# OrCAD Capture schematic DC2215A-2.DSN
size Custom; title: 40V, 2A SYNCHRONOUS STEP-DOWN REGULATOR WITH LOSSLESS POWER PATH; rev: 2; note: DEMO CIRCUIT 2215A
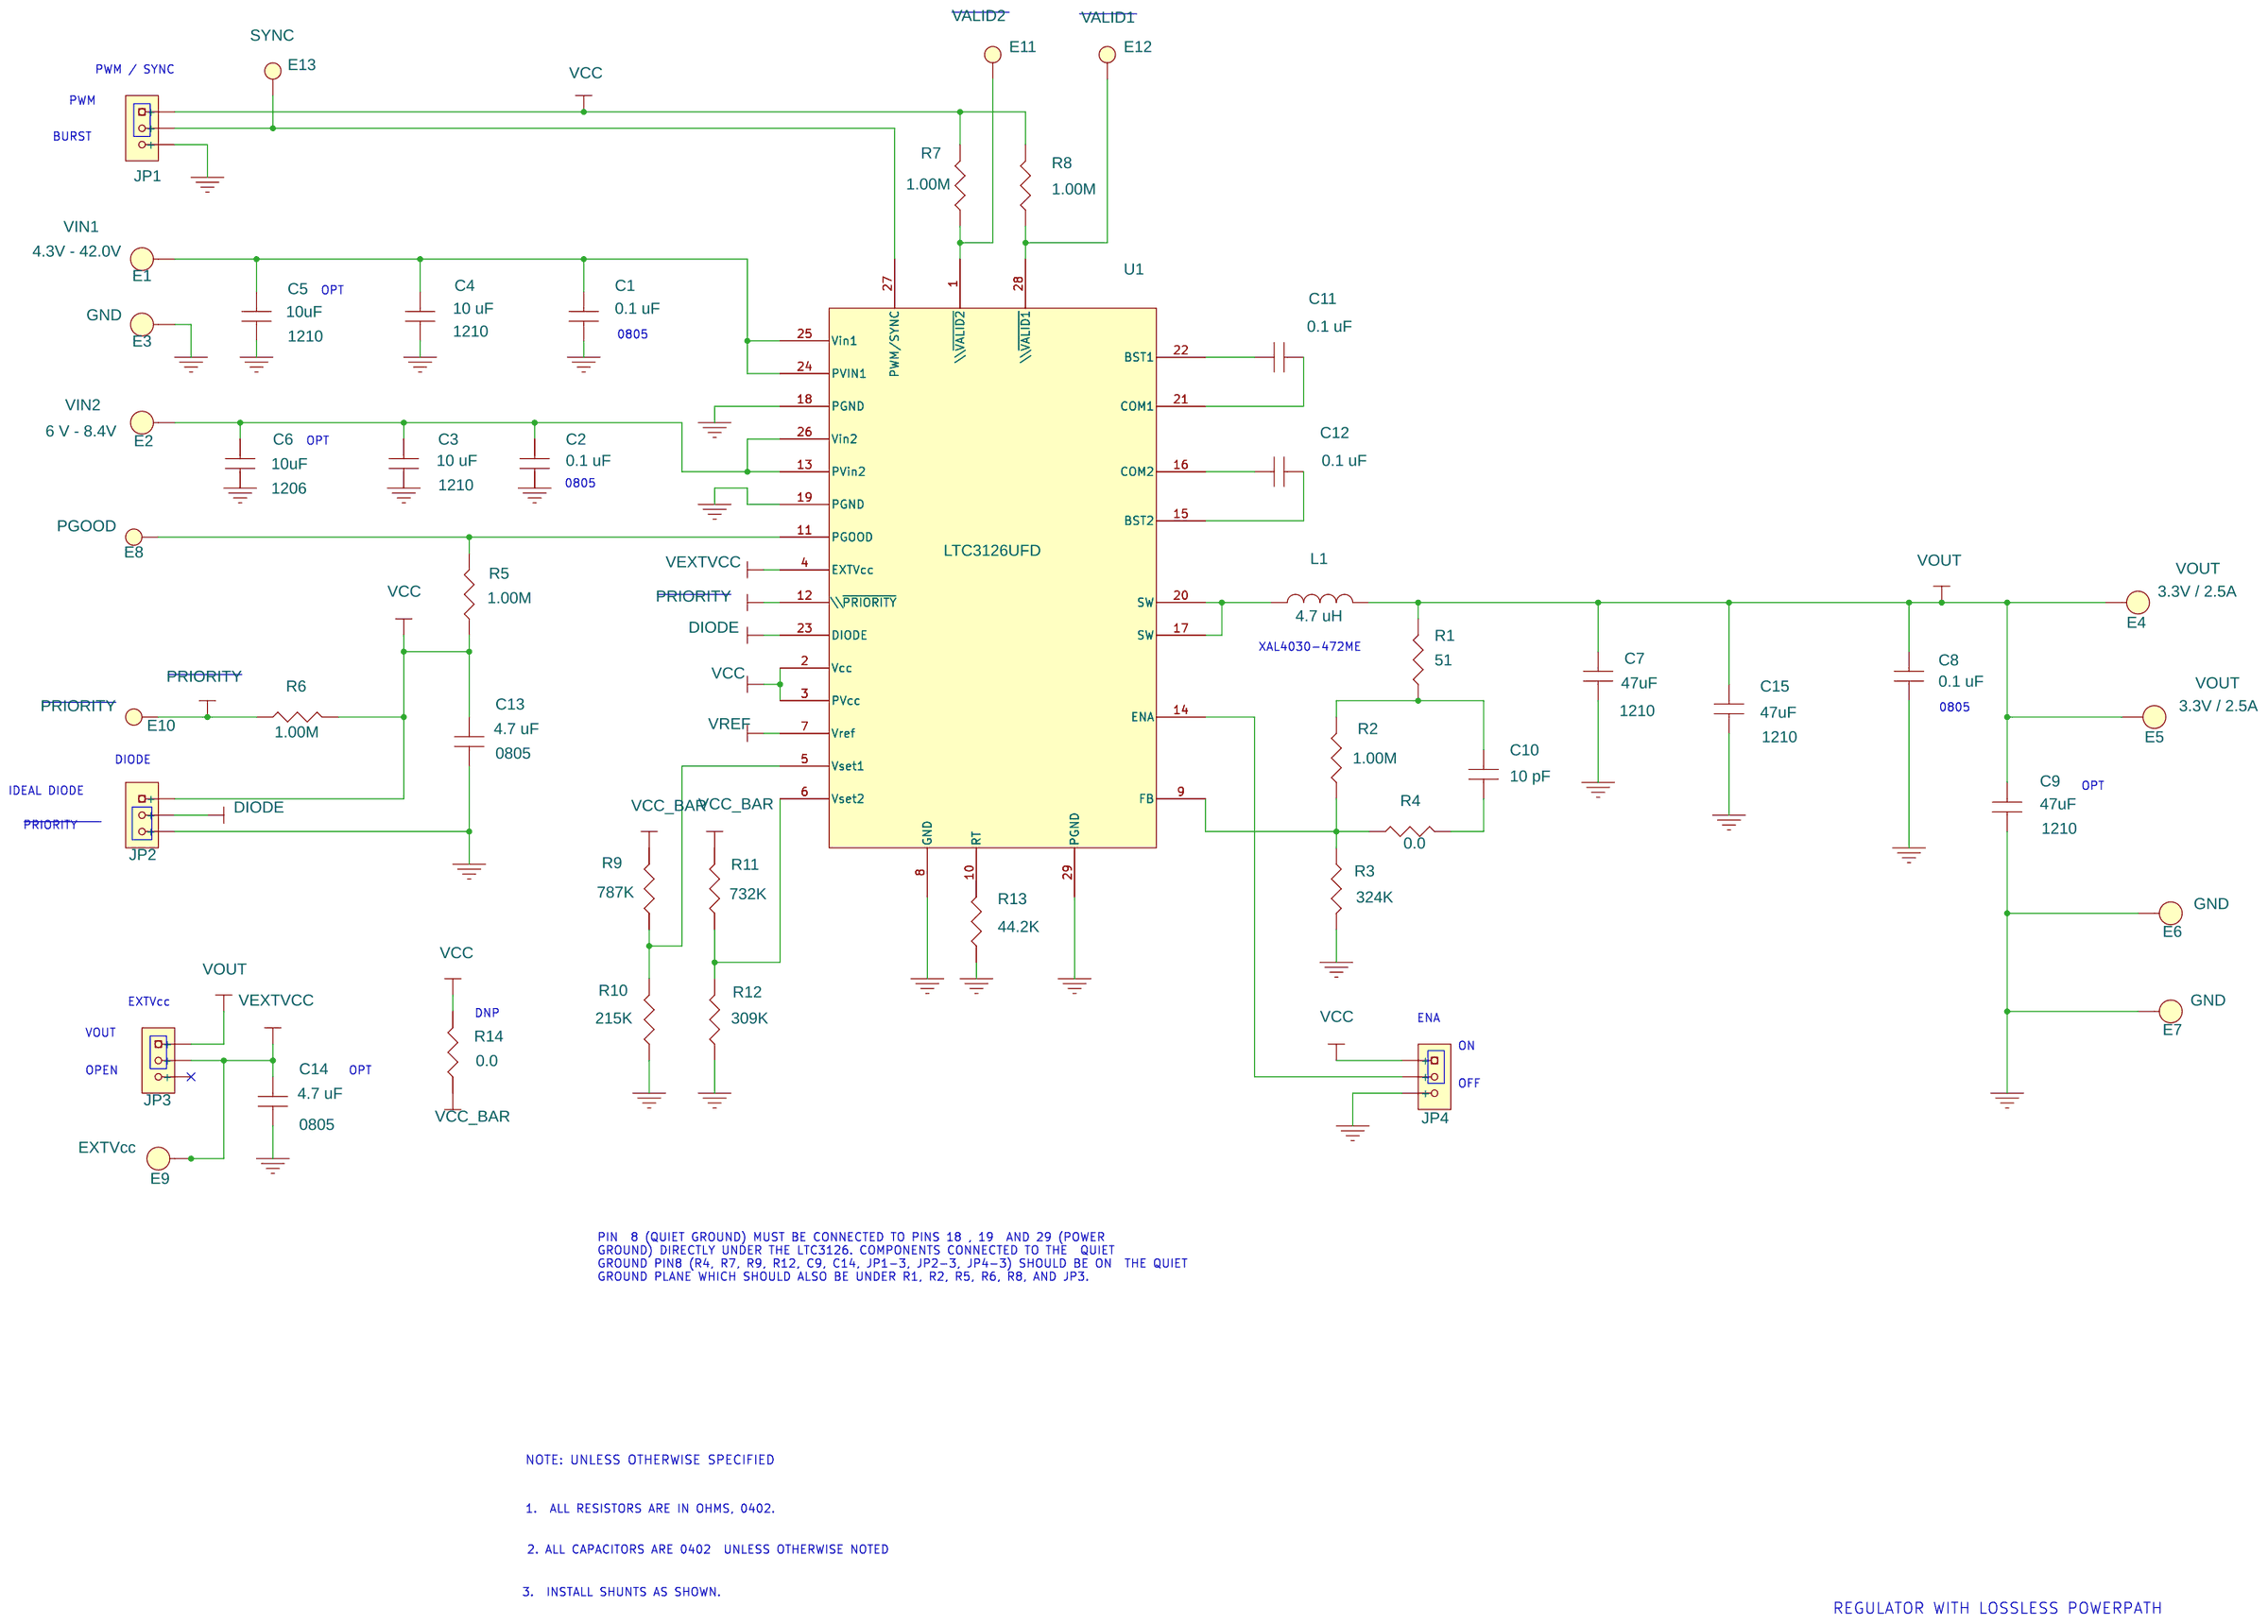
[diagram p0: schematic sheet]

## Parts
C1  0.1 uF  [0805]
C2  0.1 uF  [0805]
C3  10 uF  [1210]
C4  10 uF  [1210]
C5  10uF  [1210]
C6  10uF  [1206]
C7  47uF  [1210]
C8  0.1 uF  [0805]
C9  47uF  [1210]
C10  10 pF  [0402-SMALL]
C11  0.1 uF  [0402-SMALL]
C12  0.1 uF  [0402-SMALL]
C13  4.7 uF  [0805]
C14  4.7 uF  [0805]
C15  47uF  [1210]
E1  0.09"  [MILL-MAX-2501-2]
E2  0.09"  [MILL-MAX-2501-2]
E3  0.09"  [MILL-MAX-2501-2]
E4  0.09"  [MILL-MAX-2501-2]
E5  0.09"  [MILL-MAX-2501-2]
E6  0.09"  [MILL-MAX-2501-2]
E7  0.09"  [MILL-MAX-2501-2]
E8  PGOOD  [MILL-MAX-2308]
E9  0.09"  [MILL-MAX-2501-2]
E10  PRIORITY  [MILL-MAX-2308]
E11  VALID2  [MILL-MAX-2308]
E12  VALID1  [MILL-MAX-2308]
E13  SYNC  [MILL-MAX-2308]
JP1  ADR0  [HD1X3-079]
JP2  ADR0  [HD1X3-079]
JP3  ADR0  [HD1X3-079]
JP4  ADR0  [HD1X3-079]
L1  4.7 uH  [IND-XAL40XX]
R1  51  [0402-SMALL]
R2  1.00M  [0402-SMALL]
R3  324K  [0402-SMALL]
R4  0.0  [0402-SMALL]
R5  1.00M  [0402-SMALL]
R6  1.00M  [0402-SMALL]
R7  1.00M  [0402-SMALL]
R8  1.00M  [0402-SMALL]
R9  787K  [0402-SMALL]
R10  215K  [0402-SMALL]
R11  732K  [0402-SMALL]
R12  309K  [0402-SMALL]
R13  44.2K  [0402-SMALL]
R14  0.0  [0402-SMALL]
U1  LTC3126UFD  [LTC-UFD-28-1712]

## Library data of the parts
C1 = Capacitor_0805_2
C2 = Capacitor_0805
C3 = Capacitor_1210
C4 = Capacitor_1210_3
C5 C6 = Capacitor_1206
C7 = Capacitor_1210_1
C8 = Capacitor_0805_4
C9 = Capacitor_1210_2
C10 = CAP_0402_1
C11 = CAP_0402_2
C12 = CAP_0402
C13 = Capacitor_0805_3
C14 = Capacitor_0805_1
C15 = Capacitor_1210_4
E1 = E_2: COMPFIXED: VIN1; COMPGROUP: 4.3V - 42.0V
E2 = E_2: COMPFIXED: VIN2; COMPGROUP: 6 V - 8.4V
E3 E6 E7 = E_2: COMPFIXED: GND
E4 E5 = E_2: 1A peak: 1A peak; COMPFIXED: VOUT; COMPGROUP: 3.3V / 2.5A
E8 E10-E13 = T_POINT_R
E9 = E_2: COMPGROUP: EXTVcc
JP1-JP4 = CON6AP_6
L1 = inductor-EPLxxx
R1 = Resistor_0402_10
R2 = Resistor_0402
R3 = Resistor_0402_3
R4 = Resistor_0402_12
R5 = Resistor_0402_1
R6 = Resistor_0402_6
R7 = Resistor_0402_5
R8 = Resistor_0402_2
R9 = Resistor_0402_7
R10 = Resistor_0402_4
R11 = Resistor_0402_11
R12 = Resistor_0402_8
R13 = Resistor_0402_13
R14 = Resistor_0402_9
U1 = LTC3126-UFD

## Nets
GND_POWER: C1.2 C2.2 C3.1 C4.2 C5.2 C6.2 C7.2 C8.2 C9.2 C13.2 C14.1 C15.2 E3.1(A) E6.1(A) E7.1(A) JP1.3(+) JP2.3(+) JP4.3(+) R3.2 R10.1 R12.1 R13.1 U1.8(GND) U1.18(PGND) U1.19(PGND) U1.29(PGND)
VCC: C13.1 JP1.1(+) JP2.1(+) JP4.1(+) R5.1 R6.2 R7.2 R8.2 R14.2 U1.2(Vcc) U1.3(PVcc)
DIODE: JP2.2(+) U1.23(DIODE)
PRIORITY: E10.1(TP) R6.1 U1.12(\\~{PRIORITY})
VEXTVcc: C14.2 E9.1(A) JP3.2(+) U1.4(EXTVcc)
VOUT: C7.1 C8.1 C9.1 C15.1 E4.1(A) E5.1(A) JP3.1(+) L1.2 R1.2
Vref: R9.2 R11.2 R14.1 U1.7(Vref)
N16622621: R9.1 R10.2 U1.5(Vset1)
N16623342: R11.1 R12.2 U1.6(Vset2)
N16624249: L1.1 U1.17(SW) U1.20(SW)
N16624724: C1.1 C4.1 C5.1 E1.1(A) U1.24(PVIN1) U1.25(Vin1)
N16624747: C2.1 C3.2 C6.1 E2.1(A) U1.13(PVin2) U1.26(Vin2)
N16626076: E8.1(TP) R5.2 U1.11(PGOOD)
N16626098: E12.1(TP) R8.1 U1.28(\\~{VALID1})
N16635159: E11.1(TP) R7.1 U1.1(\\~{VALID2})
N16635930: C11.2 U1.22(BST1)
N16635934: C11.1 U1.21(COM1)
N16635941: C12.2 U1.16(COM2)
N16635945: C12.1 U1.15(BST2)
N16635957: JP4.2(+) U1.14(ENA)
N16642247: E13.1(TP) JP1.2(+) U1.27(PWM/SYNC)
N16642544: C10.2 R1.1 R2.2
N16642634: C10.1 R4.2
N16642640: R2.1 R3.1 R4.1 U1.9(FB)
N16681232: R13.2 U1.10(RT)

Not connected (* = marked no-connect by the designer): JP3 3(+)*

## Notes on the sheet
- PWM / SYNC
- PWM
- BURST
- OPT
- 0805
- OPT
- 0805
- XAL4030-472ME
- 0805
- DIODE
- IDEAL DIODE
- OPT
- PRIORITY
- EXTVcc
- DNP
- ENA
- VOUT
- ON
- OPEN
- OPT
- OFF
- PIN  8 (QUIET GROUND) MUST BE CONNECTED TO PINS 18 , 19  AND 29 (POWER
  GROUND) DIRECTLY UNDER THE LTC3126. COMPONENTS CONNECTED TO THE  QUIET
  GROUND PIN8 (R4, R7, R9, R12, C9, C14, JP1-3, JP2-3, JP4-3) SHOULD BE ON  THE QUIET
  GROUND PLANE WHICH SHOULD ALSO BE UNDER R1, R2, R5, R6, R8, AND JP3.
- NOTE: UNLESS OTHERWISE SPECIFIED
- 1.  ALL RESISTORS ARE IN OHMS, 0402.
- 2. ALL CAPACITORS ARE 0402  UNLESS OTHERWISE NOTED
- 3.  INSTALL SHUNTS AS SHOWN.
- REGULATOR WITH LOSSLESS POWERPATH
